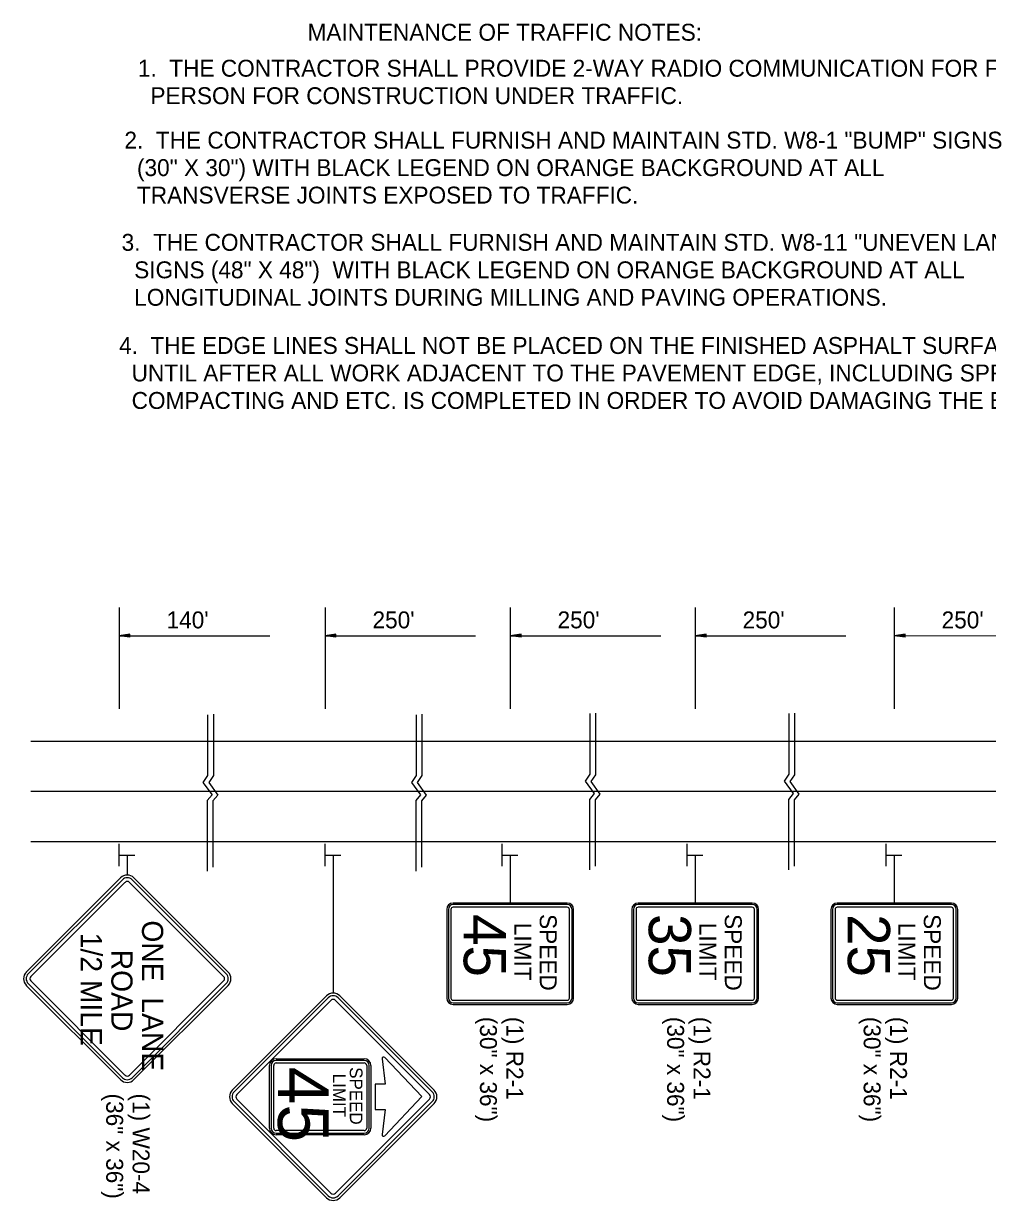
# Model space of a CAD drawing. Extents: x 1926586 to 1930787, y 596452 to 599566.
# Drawn here: x 1927867.5 to 1928209.4, y 597276.5 to 597694.1 of the extents above; entities that cross this region are included whole.
import ezdxf

# ---------------------------------------------------------------- set-up
doc = ezdxf.new("R2010")
doc.units = 0
for name, color, linetype in [('Default', 7, 'Continuous'), ('P_TC_Signs_Permanent', 7, 'Continuous'), ('P_TC_Signs_Temporary', 7, 'Continuous'), ('R_Border', 7, 'Continuous')]:
    doc.layers.add(name, color=color, linetype=linetype)

msp = doc.modelspace()

# ---------------------------------------------------------------- linework, layer by layer
at = {"layer": 'Default'}
for p, q in [((1927901.41, 597486.95), (1927901.41, 597450.9)), ((1927974.47, 597486.95), (1927974.47, 597450.92)), ((1928040.12, 597486.95), (1928040.12, 597450.92)), ((1928105.77, 597486.95), (1928105.77, 597450.92)), ((1928176.38, 597486.95), (1928176.38, 597450.92)), ((1927905.24, 597477.48), (1927901.41, 597476.91)), ((1927905.24, 597476.33), (1927901.41, 597476.91)), ((1927901.41, 597476.91), (1927954.81, 597476.91)), ((1927905.24, 597477.39), (1927902.05, 597476.91)), ((1927905.24, 597476.43), (1927902.05, 597476.91)), ((1927905.24, 597477.29), (1927902.71, 597476.91)), ((1927905.24, 597476.53), (1927902.71, 597476.91)), ((1927905.24, 597477.19), (1927903.35, 597476.91)), ((1927905.24, 597476.62), (1927903.35, 597476.91)), ((1927905.24, 597477.1), (1927904, 597476.91)), ((1927905.24, 597476.72), (1927904, 597476.91)), ((1927905.24, 597477), (1927904.64, 597476.91)), ((1927905.24, 597476.82), (1927904.64, 597476.91)), ((1927905.24, 597476.33), (1927905.24, 597477.48)), ((1927978.3, 597477.48), (1927974.47, 597476.91)), ((1927974.47, 597476.91), (1928027.87, 597476.91)), ((1927978.3, 597476.33), (1927974.47, 597476.91)), ((1927978.3, 597477.39), (1927975.11, 597476.91)), ((1927978.3, 597476.43), (1927975.11, 597476.91)), ((1927978.3, 597477.29), (1927975.77, 597476.91)), ((1927978.3, 597476.53), (1927975.77, 597476.91)), ((1927978.3, 597477.19), (1927976.41, 597476.91)), ((1927978.3, 597476.62), (1927976.41, 597476.91)), ((1927978.3, 597477.1), (1927977.06, 597476.91)), ((1927978.3, 597476.72), (1927977.06, 597476.91)), ((1927978.3, 597477), (1927977.7, 597476.91)), ((1927978.3, 597476.82), (1927977.7, 597476.91)), ((1927978.3, 597476.33), (1927978.3, 597477.48)), ((1928043.96, 597477.48), (1928040.12, 597476.91)), ((1928040.12, 597476.91), (1928093.52, 597476.91)), ((1928043.96, 597476.33), (1928040.12, 597476.91)), ((1928043.96, 597477.39), (1928040.76, 597476.91)), ((1928043.96, 597476.43), (1928040.76, 597476.91)), ((1928043.96, 597477.29), (1928041.42, 597476.91)), ((1928043.96, 597476.53), (1928041.42, 597476.91)), ((1928043.96, 597477.19), (1928042.06, 597476.91)), ((1928043.96, 597476.62), (1928042.06, 597476.91)), ((1928043.96, 597477.1), (1928042.71, 597476.91)), ((1928043.96, 597476.72), (1928042.71, 597476.91)), ((1928043.96, 597477), (1928043.35, 597476.91)), ((1928043.96, 597476.82), (1928043.35, 597476.91)), ((1928043.96, 597476.33), (1928043.96, 597477.48)), ((1928109.61, 597477.48), (1928105.77, 597476.91)), ((1928105.77, 597476.91), (1928159.17, 597476.91)), ((1928109.61, 597476.33), (1928105.77, 597476.91)), ((1928109.61, 597477.39), (1928106.41, 597476.91)), ((1928109.61, 597476.43), (1928106.41, 597476.91)), ((1928109.61, 597477.29), (1928107.07, 597476.91)), ((1928109.61, 597476.53), (1928107.07, 597476.91)), ((1928109.61, 597477.19), (1928107.71, 597476.91)), ((1928109.61, 597476.62), (1928107.71, 597476.91)), ((1928109.61, 597477.1), (1928108.36, 597476.91)), ((1928109.61, 597476.72), (1928108.36, 597476.91)), ((1928109.61, 597477), (1928109, 597476.91)), ((1928109.61, 597476.82), (1928109, 597476.91)), ((1928109.61, 597476.33), (1928109.61, 597477.48)), ((1928180.22, 597477.48), (1928176.38, 597476.91)), ((1928176.38, 597476.91), (1928229.78, 597476.93)), ((1928180.22, 597476.33), (1928176.38, 597476.91)), ((1928180.22, 597477.39), (1928177.02, 597476.91)), ((1928180.22, 597476.43), (1928177.02, 597476.91)), ((1928180.22, 597477.29), (1928177.68, 597476.91)), ((1928180.22, 597476.53), (1928177.68, 597476.91)), ((1928180.22, 597477.19), (1928178.32, 597476.91)), ((1928180.22, 597476.62), (1928178.32, 597476.91)), ((1928180.22, 597477.1), (1928178.97, 597476.91)), ((1928180.22, 597476.72), (1928178.97, 597476.91)), ((1928180.22, 597477), (1928179.61, 597476.91)), ((1928180.22, 597476.82), (1928179.61, 597476.91)), ((1928180.22, 597476.33), (1928180.22, 597477.48)), ((1927870.1, 597439.49), (1929142.12, 597439.49)), ((1927870.1, 597421.7), (1929142.12, 597421.7)), ((1927870.1, 597403.91), (1929142.12, 597403.91)), ((1927901.41, 597395.11), (1927901.41, 597403.12)), ((1927974.47, 597395.11), (1927974.47, 597403.12)), ((1928037.27, 597395.11), (1928037.27, 597403.12)), ((1928102.92, 597395.11), (1928102.92, 597403.12)), ((1928173.53, 597395.11), (1928173.53, 597403.12)), ((1927901.52, 597399.09), (1927906.99, 597399.09)), ((1927974.58, 597399.09), (1927980.05, 597399.09)), ((1928037.39, 597399.09), (1928042.85, 597399.09)), ((1928103.04, 597399.09), (1928108.5, 597399.09)), ((1928173.65, 597399.09), (1928179.11, 597399.09))]:
    msp.add_line(p, q, dxfattribs=at)
for points in [[(1927932.76, 597448.87), (1927932.76, 597427.35), (1927931.1, 597424.87), (1927934.34, 597420.44), (1927932.64, 597418.4), (1927932.63, 597393.37)], [(1927934.81, 597449.06), (1927934.81, 597427.26), (1927933.15, 597424.79), (1927936.38, 597420.36), (1927934.68, 597418.31), (1927934.68, 597394.81)], [(1928006.73, 597448.87), (1928006.73, 597427.35), (1928005.07, 597424.87), (1928008.31, 597420.44), (1928006.6, 597418.4), (1928006.6, 597393.37)], [(1928008.77, 597449.06), (1928008.77, 597427.26), (1928007.11, 597424.79), (1928010.35, 597420.36), (1928008.65, 597418.31), (1928008.64, 597394.81)], [(1928068.33, 597449.31), (1928068.33, 597427.79), (1928066.67, 597425.32), (1928069.91, 597420.89), (1928068.21, 597418.84), (1928068.2, 597393.82)], [(1928070.38, 597449.41), (1928070.38, 597427.6), (1928068.72, 597425.13), (1928071.95, 597420.7), (1928070.25, 597418.65), (1928070.25, 597395.15)], [(1928138.94, 597449.31), (1928138.94, 597427.79), (1928137.28, 597425.32), (1928140.52, 597420.89), (1928138.82, 597418.84), (1928138.81, 597393.82)], [(1928140.99, 597449.41), (1928140.99, 597427.6), (1928139.33, 597425.13), (1928142.56, 597420.7), (1928140.86, 597418.65), (1928140.86, 597395.15)]]:
    msp.add_lwpolyline(points, dxfattribs=at)
at = {"layer": 'P_TC_Signs_Permanent'}
for p, q in [((1928060.37, 597382.07), (1928019.87, 597382.07)), ((1928126.02, 597382.07), (1928085.52, 597382.07)), ((1928196.63, 597382.07), (1928156.13, 597382.07)), ((1928017.62, 597379.82), (1928017.62, 597348.32)), ((1928018.18, 597379.82), (1928018.18, 597348.32)), ((1928019.12, 597379.82), (1928019.12, 597348.32)), ((1928060.37, 597381.51), (1928019.87, 597381.51)), ((1928060.37, 597380.57), (1928019.87, 597380.57)), ((1928061.12, 597348.32), (1928061.12, 597379.82)), ((1928062.06, 597348.32), (1928062.06, 597379.82)), ((1928062.62, 597348.32), (1928062.62, 597379.82)), ((1928083.27, 597379.82), (1928083.27, 597348.32)), ((1928083.83, 597379.82), (1928083.83, 597348.32)), ((1928084.77, 597379.82), (1928084.77, 597348.32)), ((1928126.02, 597381.5), (1928085.52, 597381.5)), ((1928126.02, 597380.57), (1928085.52, 597380.57)), ((1928126.77, 597348.32), (1928126.77, 597379.82)), ((1928127.71, 597348.32), (1928127.71, 597379.82)), ((1928128.27, 597348.32), (1928128.27, 597379.82)), ((1928153.88, 597379.82), (1928153.88, 597348.32)), ((1928154.44, 597379.82), (1928154.44, 597348.32)), ((1928155.38, 597379.82), (1928155.38, 597348.32)), ((1928196.63, 597381.5), (1928156.13, 597381.5)), ((1928196.63, 597380.57), (1928156.13, 597380.57)), ((1928197.38, 597348.32), (1928197.38, 597379.82)), ((1928198.32, 597348.32), (1928198.32, 597379.82)), ((1928198.88, 597348.32), (1928198.88, 597379.82)), ((1927974.93, 597349.12), (1927941.52, 597315.71)), ((1928013.11, 597315.71), (1927979.7, 597349.12)), ((1927975.59, 597348.45), (1927942.18, 597315.04)), ((1927976.52, 597347.53), (1927943.11, 597314.12)), ((1928011.52, 597314.12), (1927978.11, 597347.53)), ((1928012.45, 597315.04), (1927979.04, 597348.45)), ((1928019.87, 597347.57), (1928060.37, 597347.57)), ((1928019.87, 597346.63), (1928060.37, 597346.63)), ((1928019.87, 597346.07), (1928060.37, 597346.07)), ((1928085.52, 597347.57), (1928126.02, 597347.57)), ((1928085.52, 597346.63), (1928126.02, 597346.63)), ((1928085.52, 597346.07), (1928126.02, 597346.07)), ((1928156.13, 597347.57), (1928196.63, 597347.57)), ((1928156.13, 597346.63), (1928196.63, 597346.63)), ((1928156.13, 597346.07), (1928196.63, 597346.07)), ((1927954.72, 597302.22), (1927954.72, 597324.42)), ((1927957.12, 597326.82), (1927988.32, 597326.82)), ((1927990.72, 597324.42), (1927990.72, 597302.22)), ((1927942.18, 597311.6), (1927975.59, 597278.19)), ((1927943.11, 597312.53), (1927976.52, 597279.11)), ((1927978.11, 597279.11), (1928011.52, 597312.53)), ((1927979.04, 597278.19), (1928012.45, 597311.6)), ((1927941.52, 597310.93), (1927974.93, 597277.52)), ((1927979.7, 597277.52), (1928013.11, 597310.93)), ((1927988.32, 597299.82), (1927957.12, 597299.82))]:
    msp.add_line(p, q, dxfattribs=at)
for points in [[(1927955.32, 597324.42), (1927955.32, 597302.22)], [(1927956.22, 597302.22), (1927956.22, 597324.42)], [(1927988.32, 597326.22), (1927957.12, 597326.22)], [(1927957.12, 597325.32), (1927988.32, 597325.32)], [(1927989.22, 597324.42), (1927989.22, 597313.32), (1927989.22, 597302.22)], [(1927990.12, 597302.22), (1927990.12, 597313.32), (1927990.12, 597324.42)], [(1927994.67, 597326.78), (1927995.79, 597317.82), (1927992.22, 597317.82), (1927992.22, 597308.82), (1927995.78, 597308.82), (1927994.67, 597299.93)], [(1927995.64, 597299.48), (1928008.72, 597313.36), (1927995.64, 597327.24)], [(1927988.32, 597301.32), (1927957.12, 597301.32)], [(1927957.12, 597300.42), (1927988.32, 597300.42)]]:
    msp.add_lwpolyline(points, dxfattribs=at)
for centre, radius, start, end in [((1928019.87, 597379.82), 2.25, 90, 180), ((1928060.37, 597379.82), 2.25, 360, 90), ((1928085.52, 597379.82), 2.25, 90, 180), ((1928126.02, 597379.82), 2.25, 360, 90), ((1928156.13, 597379.82), 2.25, 90, 180), ((1928196.63, 597379.82), 2.25, 360, 90), ((1928019.87, 597379.82), 1.69, 90, 180), ((1928019.87, 597379.82), 0.75, 90, 180), ((1928060.37, 597379.82), 1.69, 360, 90), ((1928060.37, 597379.82), 0.75, 360, 90), ((1928085.52, 597379.82), 1.69, 90, 180), ((1928085.52, 597379.82), 0.75, 90, 180), ((1928126.02, 597379.82), 1.69, 360, 90), ((1928126.02, 597379.82), 0.75, 360, 90), ((1928156.13, 597379.82), 1.69, 90, 180), ((1928156.13, 597379.82), 0.75, 90, 180), ((1928196.63, 597379.82), 1.69, 360, 90), ((1928196.63, 597379.82), 0.75, 360, 90), ((1927977.32, 597346.73), 3.37, 45, 135), ((1927977.32, 597346.73), 2.44, 45, 135), ((1927977.32, 597346.73), 1.13, 45, 135), ((1928019.87, 597348.32), 2.25, 180, 270), ((1928019.87, 597348.32), 1.69, 180, 270), ((1928019.87, 597348.32), 0.75, 180, 270), ((1928060.37, 597348.32), 2.25, 270, 360), ((1928060.37, 597348.32), 1.69, 270, 360), ((1928060.37, 597348.32), 0.75, 270, 360), ((1928085.52, 597348.32), 2.25, 180, 270), ((1928085.52, 597348.32), 1.69, 180, 270), ((1928085.52, 597348.32), 0.75, 180, 270), ((1928126.02, 597348.32), 2.25, 270, 360), ((1928126.02, 597348.32), 1.69, 270, 360), ((1928126.02, 597348.32), 0.75, 270, 360), ((1928156.13, 597348.32), 2.25, 180, 270), ((1928156.13, 597348.32), 1.69, 180, 270), ((1928156.13, 597348.32), 0.75, 180, 270), ((1928196.63, 597348.32), 2.25, 270, 360), ((1928196.63, 597348.32), 1.69, 270, 360), ((1928196.63, 597348.32), 0.75, 270, 360), ((1927957.12, 597324.42), 2.4, 90, 180), ((1927957.12, 597324.42), 1.8, 90, 180), ((1927957.12, 597324.42), 0.9, 90, 180), ((1927988.32, 597324.42), 2.4, 360, 90), ((1927988.32, 597324.42), 1.8, 360, 90), ((1927988.32, 597324.42), 0.9, 360, 90), ((1927995.23, 597326.85), 0.563, 43.3117, 187.125), ((1927943.91, 597313.32), 3.37, 135, 225), ((1928010.73, 597313.32), 3.37, 315, 45), ((1927943.91, 597313.32), 2.44, 135, 225), ((1927943.91, 597313.32), 1.13, 135, 225), ((1928010.73, 597313.32), 1.13, 315, 45), ((1928010.73, 597313.32), 2.44, 315, 45), ((1927957.12, 597302.22), 2.4, 180, 270), ((1927957.12, 597302.22), 1.8, 180, 270), ((1927957.12, 597302.22), 0.9, 180, 270), ((1927988.32, 597302.22), 2.4, 270, 360), ((1927988.32, 597302.22), 1.8, 270, 360), ((1927988.32, 597302.22), 0.9, 270, 360), ((1927995.23, 597299.86), 0.563, 172.875, 316.6883), ((1927977.32, 597279.91), 2.44, 225, 315), ((1927977.32, 597279.91), 1.13, 225, 315), ((1927977.32, 597279.91), 3.38, 225, 315)]:
    msp.add_arc(centre, radius, start, end, dxfattribs=at)
at = {"layer": 'P_TC_Signs_Temporary'}
for p, q in [((1927868.46, 597357.58), (1927901.87, 597390.99)), ((1927869.12, 597356.92), (1927902.53, 597390.33)), ((1927905.98, 597390.33), (1927939.39, 597356.92)), ((1927906.64, 597390.99), (1927940.05, 597357.58)), ((1927870.05, 597355.99), (1927903.46, 597389.4)), ((1927905.05, 597389.4), (1927938.46, 597355.99)), ((1927901.87, 597319.4), (1927868.46, 597352.81)), ((1927902.53, 597320.06), (1927869.12, 597353.47)), ((1927903.46, 597320.99), (1927870.05, 597354.4)), ((1927938.46, 597354.4), (1927905.05, 597320.99)), ((1927939.39, 597353.47), (1927905.98, 597320.06)), ((1927940.05, 597352.81), (1927906.64, 597319.4))]:
    msp.add_line(p, q, dxfattribs=at)
for centre, radius, start, end in [((1927904.26, 597388.61), 3.37, 45, 135), ((1927904.26, 597388.61), 2.44, 45, 135), ((1927904.26, 597388.61), 1.12, 45, 135), ((1927870.85, 597355.2), 3.37, 135, 225), ((1927870.85, 597355.2), 2.44, 135, 225), ((1927937.67, 597355.2), 2.44, 315, 45), ((1927937.67, 597355.2), 3.37, 315, 45), ((1927870.85, 597355.2), 1.13, 135, 225), ((1927937.67, 597355.2), 1.13, 315, 45), ((1927904.26, 597321.79), 3.37, 225, 315), ((1927904.26, 597321.79), 2.44, 225, 315), ((1927904.26, 597321.79), 1.12, 225, 315)]:
    msp.add_arc(centre, radius, start, end, dxfattribs=at)
at = {"layer": 'R_Border'}
for p, q in [((1927904.26, 597399.09), (1927904.26, 597391.98)), ((1927977.32, 597399.09), (1927977.32, 597350.11)), ((1928040.12, 597399.09), (1928040.12, 597382.07)), ((1928105.77, 597399.09), (1928105.77, 597382.07)), ((1928176.38, 597399.09), (1928176.38, 597382.07))]:
    msp.add_line(p, q, dxfattribs=at)

# ---------------------------------------------------------------- texts
at = {"layer": 'Default'}
for s, p in [("140'", (1927918.21, 597479.5)), ("250'", (1927991.27, 597479.52)), ("250'", (1928056.92, 597479.52)), ("250'", (1928122.57, 597479.5)), ("250'", (1928193.18, 597479.5))]:
    msp.add_text(s, height=6, rotation=360, dxfattribs=at).set_placement(p)
at = {"layer": 'P_TC_Signs_Permanent'}
for s, height, p in [('SPEED', 6, (1928050.62, 597378.14)), ('SPEED', 6, (1928116.27, 597378.14)), ('SPEED', 6, (1928186.88, 597378.14)), ('45', 15, (1928023.62, 597378.15)), ('LIMIT', 6, (1928041.62, 597375.05)), ('35', 15, (1928089.27, 597378.15)), ('LIMIT', 6, (1928107.27, 597375.05)), ('25', 15, (1928159.88, 597378.15)), ('LIMIT', 6, (1928177.88, 597375.05)), ('SPEED', 4.5, (1927983.22, 597323.82)), ('45', 18, (1927957.72, 597324)), ('LIMIT', 4.5, (1927977.22, 597321.51))]:
    msp.add_text(s, height=height, rotation=270, dxfattribs=at).set_placement(p)
at = {"layer": 'P_TC_Signs_Temporary'}
for s, p in [('ONE  LANE', (1927909.51, 597375.9)), ('1/2 MILE', (1927887.76, 597371.51)), ('ROAD', (1927898.63, 597365.5))]:
    msp.add_text(s, height=7.5, rotation=270, dxfattribs=at).set_placement(p)
at = {"layer": 'R_Border'}
for s, height, rotation, p in [('MAINTENANCE OF TRAFFIC NOTES:', 6, 360, (1927968.22, 597688)), ('1.  THE CONTRACTOR SHALL PROVIDE 2-WAY RADIO COMMUNICATION FOR FLAG ', 6, 360, (1927908.03, 597675.24)), ('  PERSON FOR CONSTRUCTION UNDER TRAFFIC.', 6, 360, (1927908.03, 597665.49)), ('2.  THE CONTRACTOR SHALL FURNISH AND MAINTAIN STD. W8-1 "BUMP" SIGNS', 6, 360, (1927903.26, 597649.72)), ('  (30" X 30") WITH BLACK LEGEND ON ORANGE BACKGROUND AT ALL ', 6, 360, (1927903.26, 597639.97)), ('  TRANSVERSE JOINTS EXPOSED TO TRAFFIC.', 6, 360, (1927903.26, 597630.22)), ('3.  THE CONTRACTOR SHALL FURNISH AND MAINTAIN STD. W8-11 "UNEVEN LANES" ', 6, 360, (1927902.27, 597613.46)), ('  SIGNS (48" X 48")  WITH BLACK LEGEND ON ORANGE BACKGROUND AT ALL ', 6, 360, (1927902.27, 597603.71)), ('  LONGITUDINAL JOINTS DURING MILLING AND PAVING OPERATIONS.', 6, 360, (1927902.27, 597593.96)), ('4.  THE EDGE LINES SHALL NOT BE PLACED ON THE FINISHED ASPHALT SURFACE', 6, 360, (1927901.36, 597576.87)), ('  UNTIL AFTER ALL WORK ADJACENT TO THE PAVEMENT EDGE, INCLUDING SPREADING,', 6, 360, (1927901.36, 597567.12)), ('  COMPACTING AND ETC. IS COMPLETED IN ORDER TO AVOID DAMAGING THE EDGE LINES.', 6, 360, (1927901.36, 597557.37)), ('(30" x 36")', 5.9996, 270, (1928029.4, 597341.69)), ('(1) R2-1', 6, 270, (1928038.76, 597341.69)), ('(30" x 36")', 5.9996, 270, (1928095.81, 597341.69)), ('(1) R2-1', 6, 270, (1928105.18, 597341.69)), ('(30" x 36")', 5.9996, 270, (1928165.53, 597341.69)), ('(1) R2-1', 6, 270, (1928174.89, 597341.69)), ('(36" x 36")', 5.9996, 270, (1927896.81, 597314.47)), ('(1) W20-4', 6, 270, (1927906.17, 597314.47))]:
    msp.add_text(s, height=height, rotation=rotation, dxfattribs=at).set_placement(p)

doc.saveas('drawing.dxf')
